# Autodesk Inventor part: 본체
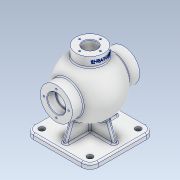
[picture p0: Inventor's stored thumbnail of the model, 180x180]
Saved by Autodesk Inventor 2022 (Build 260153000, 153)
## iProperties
Created: 2024-04
Part Number: 본체
Material: 알루미늄 6061
Document SubType Name: Modeling
Designer: Admin
Mass: 1526.79 g
Surface Area: 1175.06 cm^2
Volume: 565.478 cm^3
Density: 2.7 g/cm^3
Appearance: 알루미늄 - 평지
Author: Admin
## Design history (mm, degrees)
sketch "스케치1"
  geometry: L1 (0, 75.6)-(0, -75.6) reference; A1 r 54 centre (0, 0) between (0, -54) and (0, 54); 1 further point
  constraints: 2 point on circle, 2 point on line, 1 centre point, 1 coincident
  dimensions: "d0" = 108 diameter of A1
revolve "회전1" sketch "스케치1" stored, may be unused: angle "d1" = 90 deg
node "작업 평면1"
sketch "스케치2"
  geometry: C1 r 27 at (0, 0); 1 further point
  constraints: 1 centre point, 1 coincident
  dimensions: "d3" = 54 diameter of C1
extrude "돌출1" join sketch "스케치2" stored distance "d4" = 10; taper "d5" = 0 deg
sketch "스케치3"
  geometry: C1 r 31 at (0, 0); 1 further point
  constraints: 1 centre point, 1 coincident
  dimensions: "d6" = 62 diameter of C1
extrude "돌출2" join sketch "스케치3" stored distance "d7" = 130; taper "d8" = 0 deg
node "작업 평면2"
sketch "스케치4"
  geometry: L1 (-62.5, -62.5)-(62.5, -62.5); L2 (62.5, -62.5)-(62.5, 62.5); L3 (62.5, 62.5)-(-62.5, 62.5); L4 (-62.5, 62.5)-(-62.5, -62.5); L5 (-62.5, -62.5)-(62.5, 62.5); L6 (62.5, -62.5)-(-62.5, 62.5); C1 r 27 at (0, 0) reference; 1 further point
  constraints: 12 end point, 2 midpoint, 2 parallel, 1 horizontal, 1 perpendicular
  dimensions: "d10" = 125 distance of L1.end L2.end; "d11" = 125 distance of L2.end L3.end
extrude "돌출3" join sketch "스케치4" distance "d12" = 10; taper "d13" = 0 deg
sketch "스케치5"
  geometry: L1 (-75, 62.5)-(-75, -62.5) reference; L2 (-75, 50.5)-(-27.028, 33.04); L3 (-27.028, 33.04)-(-27.028, -33.04); L4 (-27.028, -33.04)-(-75, -50.5); L5 (-115, 0)-(95, 0) reference; L6 (-85, 62.5)-(-75, 62.5) reference; 1 further point
  constraints: 6 end point, 2 point on line, 1 vertical, 1 other
  dimensions: "d14" = 20 deg angle of L6 L2; "d15" = 12 distance of L1.start L2.start; "d16" = 66.07926 distance of L2.end L3.end
extrude "돌출4" join sketch "스케치5" stored distance "d17" = 8; taper "d18" = 0 deg
sketch "스케치6"
  geometry: L1 (-62.5, -75)-(62.5, -75) reference; L2 (-50.5, -75)-(-35.02, -32.47); L3 (-35.02, -32.47)-(35.02, -32.47); L4 (35.02, -32.47)-(50.5, -75); L5 (0, -115)-(0, 95) reference; L6 (62.5, -85)-(62.5, -75) reference; 1 further point
  constraints: 6 end point, 2 point on line, 1 horizontal, 1 other
  dimensions: "d19" = 20 deg angle of L6 L4; "d20" = 12 distance of L1.end L4.end; "d21" = 70.04097 distance of L2.end L3.end
extrude "돌출5" join sketch "스케치6" stored distance "d22" = 8; taper "d23" = 0 deg
sketch "스케치7"
  geometry: L1 (0, -91)-(0, 91) reference; A1 r 44 centre (0, 0) between (0, -44) and (0, 44); 1 further point
  constraints: 2 point on circle, 2 point on line, 1 centre point, 1 coincident
  dimensions: "d24" = 88 diameter of A1
revolve "회전2" sketch "스케치7" stored, may be unused: angle "d25" = 90 deg
sketch "스케치8"
  geometry: C1 r 13 at (0, 0); 1 further point
  constraints: 1 centre point, 1 coincident
  dimensions: "d26" = 26 diameter of C1
extrude "돌출6" cut sketch "스케치8" stored distance "d27" = 8; taper "d28" = 0 deg
sketch "스케치9"
  geometry: C1 r 17.5 at (0, 0); 1 further point
  constraints: 1 centre point, 1 coincident
  dimensions: "d29" = 35 diameter of C1
extrude "돌출7" cut sketch "스케치9" distance "d30" = 16; taper "d31" = 0 deg
sketch "스케치10"
  geometry: C1 r 15 at (0, 0); 1 further point
  constraints: 1 centre point, 1 coincident
  dimensions: "d32" = 30 diameter of C1
extrude "돌출8" cut sketch "스케치10" stored distance "d33" = 16; taper "d34" = 0 deg
sketch "스케치11" dims "d35" = 48
  geometry: L1 (-87.5, 0)-(87.5, 0) reference; C1 r 15 at (0, 0) reference; 3 further points
  constraints: 1 coincident, 1 horizontal alignment, 1 point on line, 2 other
hole "구멍1" sketch "스케치11" at (24, 0) diameter "d36" = 3.242; stored, may be unused: countersink angle "d40" = 90 deg, drill point angle "d42" = 118 deg; dims "d37" = 12, "d38" = 4, "d39" = 2, "d41" = 15
sketch "스케치12" dims "d46" = 40
  geometry: L1 (-87.5, 0)-(87.5, 0) reference; 3 further points
  constraints: 1 coincident, 1 horizontal alignment, 1 point on line, 2 other
hole "구멍2" sketch "스케치12" at (-20, 0) diameter "d47" = 3.242; stored, may be unused: countersink angle "d51" = 90 deg, drill point angle "d53" = 118 deg; dims "d48" = 9, "d49" = 4, "d50" = 2, "d52" = 11
fillet "모깎기1" dims "d57" = 16
sketch "스케치13"
  geometry: L1 (-46.5, -62.5)-(46.5, -62.5) reference; L2 (62.5, -46.5)-(62.5, 46.5) reference; L3 (46.5, 62.5)-(-46.5, 62.5) reference; L4 (-62.5, 46.5)-(-62.5, -46.5) reference; L5 (50.5, -4)-(4, -4) reference; L6 (4, -4)-(4, -50.5) reference; L7 (4, -50.5)-(-4, -50.5) reference; L8 (-4, -50.5)-(-4, -4) reference; L9 (-4, -4)-(-50.5, -4) reference; L10 (-50.5, -4)-(-50.5, 4) reference; L11 (-50.5, 4)-(-4, 4) reference; L12 (-4, 4)-(-4, 50.5) reference; L13 (-4, 50.5)-(4, 50.5) reference; L14 (4, 50.5)-(4, 4) reference; L15 (4, 4)-(50.5, 4) reference; L16 (50.5, 4)-(50.5, -4) reference; A1 r 16 centre (-46.5, -46.5) between (-62.5, -46.5) and (-46.5, -62.5) reference; A2 r 16 centre (46.5, -46.5) between (46.5, -62.5) and (62.5, -46.5) reference; A3 r 16 centre (46.5, 46.5) between (62.5, 46.5) and (46.5, 62.5) reference; A4 r 16 centre (-46.5, 46.5) between (-46.5, 62.5) and (-62.5, 46.5) reference; 5 further points
  constraints: 4 coincident
hole "구멍3" sketch "스케치13" at (-46.5, 46.5), (-46.5, -46.5), (46.5, -46.5), (46.5, 46.5) diameter "d58" = 11; stored, may be unused: countersink angle "d62" = 90 deg, drill point angle "d64" = 118 deg; dims "d59" = 9, "d60" = 4, "d61" = 2, "d63" = 11
chamfer "모따기1" distance "d65" = 1; stored, may be unused: second distance "d66" = 2, angle "d67" = 45 deg
fillet "모깎기2" dims "d68" = 0.6
fillet "모깎기3" dims "d69" = 3
fillet "모깎기4" dims "d70" = 3
fillet "모깎기5" dims "d71" = 3
fillet "모깎기6" dims "d72" = 3
node "작업 평면3"
sketch "스케치14"
  geometry: L1 (65, -27)-(65, 27) reference; L2 (-115, 0)-(95, 0) reference; 2 further points
  constraints: 1 point on line, 1 other
  dimensions: "d74" = 9 distance from line of L1 point (56, 0)
feature "엠보싱1" sketch "스케치14" dims "d10" = 125, "d11" = 125, "d75" = 1, "d76" = 0
node "솔리드1"
mirror "미러1"
pattern_circular "원형 패턴1" dims angle "d44" = 360 deg
mirror "미러2"
pattern_circular "원형 패턴2" dims angle "d55" = 360 deg
node "투영된 루프1"
feature "A9D066F2-1C7D-4E18-AEED-F7BC21143FA4" dims "d58" = 11, "d59" = 9, "d60" = 4, "d61" = 2, "d62" = 90 deg, "d63" = 11, "d64" = 118 deg
other parameters: "d2" = 65, "d9" = -85, "d73" = 75
